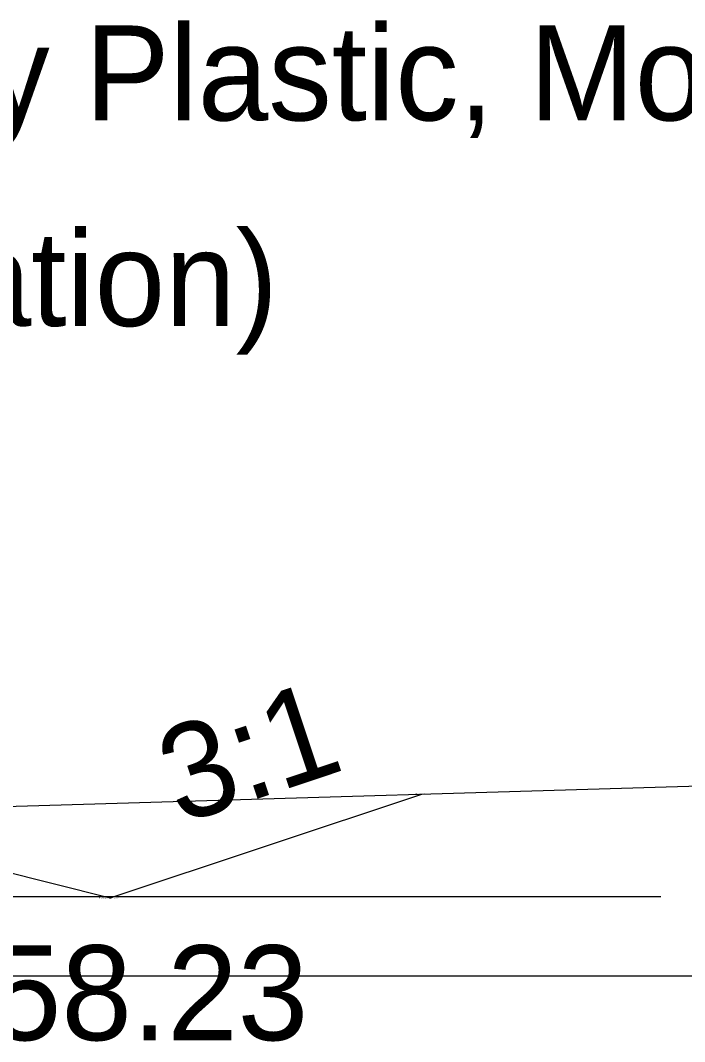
# Model space of a CAD drawing. Extents: x -516 to 303, y -10 to 5017.
# Drawn here: x 179.58 to 190.08, y 3498.96 to 3515.1 of the extents above; entities that cross this region are included whole.
import ezdxf

# ---------------------------------------------------------------- set-up
doc = ezdxf.new("R2010")
doc.units = 0
for name, color, linetype in [('Exist Cross Section Cell', 7, 'Continuous'), ('Exist XS Ground Line', 7, 'Continuous'), ('Prop CMT Slope Grass', 7, 'Continuous'), ('Prop Road Sect_ Material - Contact (General - Minor)', 7, 'Continuous'), ('Prop Road Sect_ Material - Tx (Composite Desc)', 7, 'Continuous'), ('Prop XS Ditch Standard Text', 7, 'Continuous'), ('Prop XS Side Slope Text', 7, 'Continuous'), ('Scratch_Level_0', 7, 'Continuous')]:
    doc.layers.add(name, color=color, linetype=linetype)

msp = doc.modelspace()

# ---------------------------------------------------------------- linework, layer by layer
at = {"layer": 'Exist Cross Section Cell'}
msp.add_line((150, 3500), (300, 3500), dxfattribs=at)
at = {"layer": 'Exist XS Ground Line'}
msp.add_lwpolyline([(165.952, 3503.61), (166.307, 3503.585), (167.227, 3503.495), (176.847, 3502.602), (194.221, 3503.118), (195.361, 3503.096), (195.861, 3503.156), (197.361, 3503.152), (207.496, 3503.123)], dxfattribs=at)
at = {"layer": 'Prop CMT Slope Grass'}
for p, q in [((173, 3503.231), (181, 3501.231)), ((181, 3501.231), (185.923, 3502.871))]:
    msp.add_line(p, q, dxfattribs=at)
at = {"layer": 'Prop Road Sect_ Material - Contact (General - Minor)'}
msp.add_line((112.368, 3501.254), (189.704, 3501.254), dxfattribs=at)

# ---------------------------------------------------------------- texts
at = {"layer": 'Prop Road Sect_ Material - Tx (Composite Desc)'}
for s, p in [('ROADWAY EMBANKMENT: Brown, Medium Stiff to Stiff, Silty CLAY (A-7-6), Highly Plastic, Moist', (105.475, 3513.518)), ('COASTAL PLAIN: Black to Gray, Stiff, Sandy SILT (A-4), Moist (Black Creek Formation)', (105.4, 3510.268))]:
    msp.add_text(s, height=1.5, dxfattribs=at).set_placement(p)
at = {"layer": 'Prop XS Ditch Standard Text'}
msp.add_text('158.23', height=1.5, dxfattribs=at).set_placement((177.995, 3498.981))
at = {"layer": 'Prop XS Side Slope Text'}
msp.add_text('3:1', height=1.5, rotation=18.4332, dxfattribs=at).set_placement((182.096, 3502.387))
at = {"layer": 'Scratch_Level_0'}
for s, p in [('RT_Slope_Cut', (185.819, 3502.861)), ('RT_SS_Ditch_Base_Out', (180.82, 3501.221))]:
    msp.add_text(s, height=0.02, dxfattribs=at).set_placement(p)

doc.saveas('drawing.dxf')
